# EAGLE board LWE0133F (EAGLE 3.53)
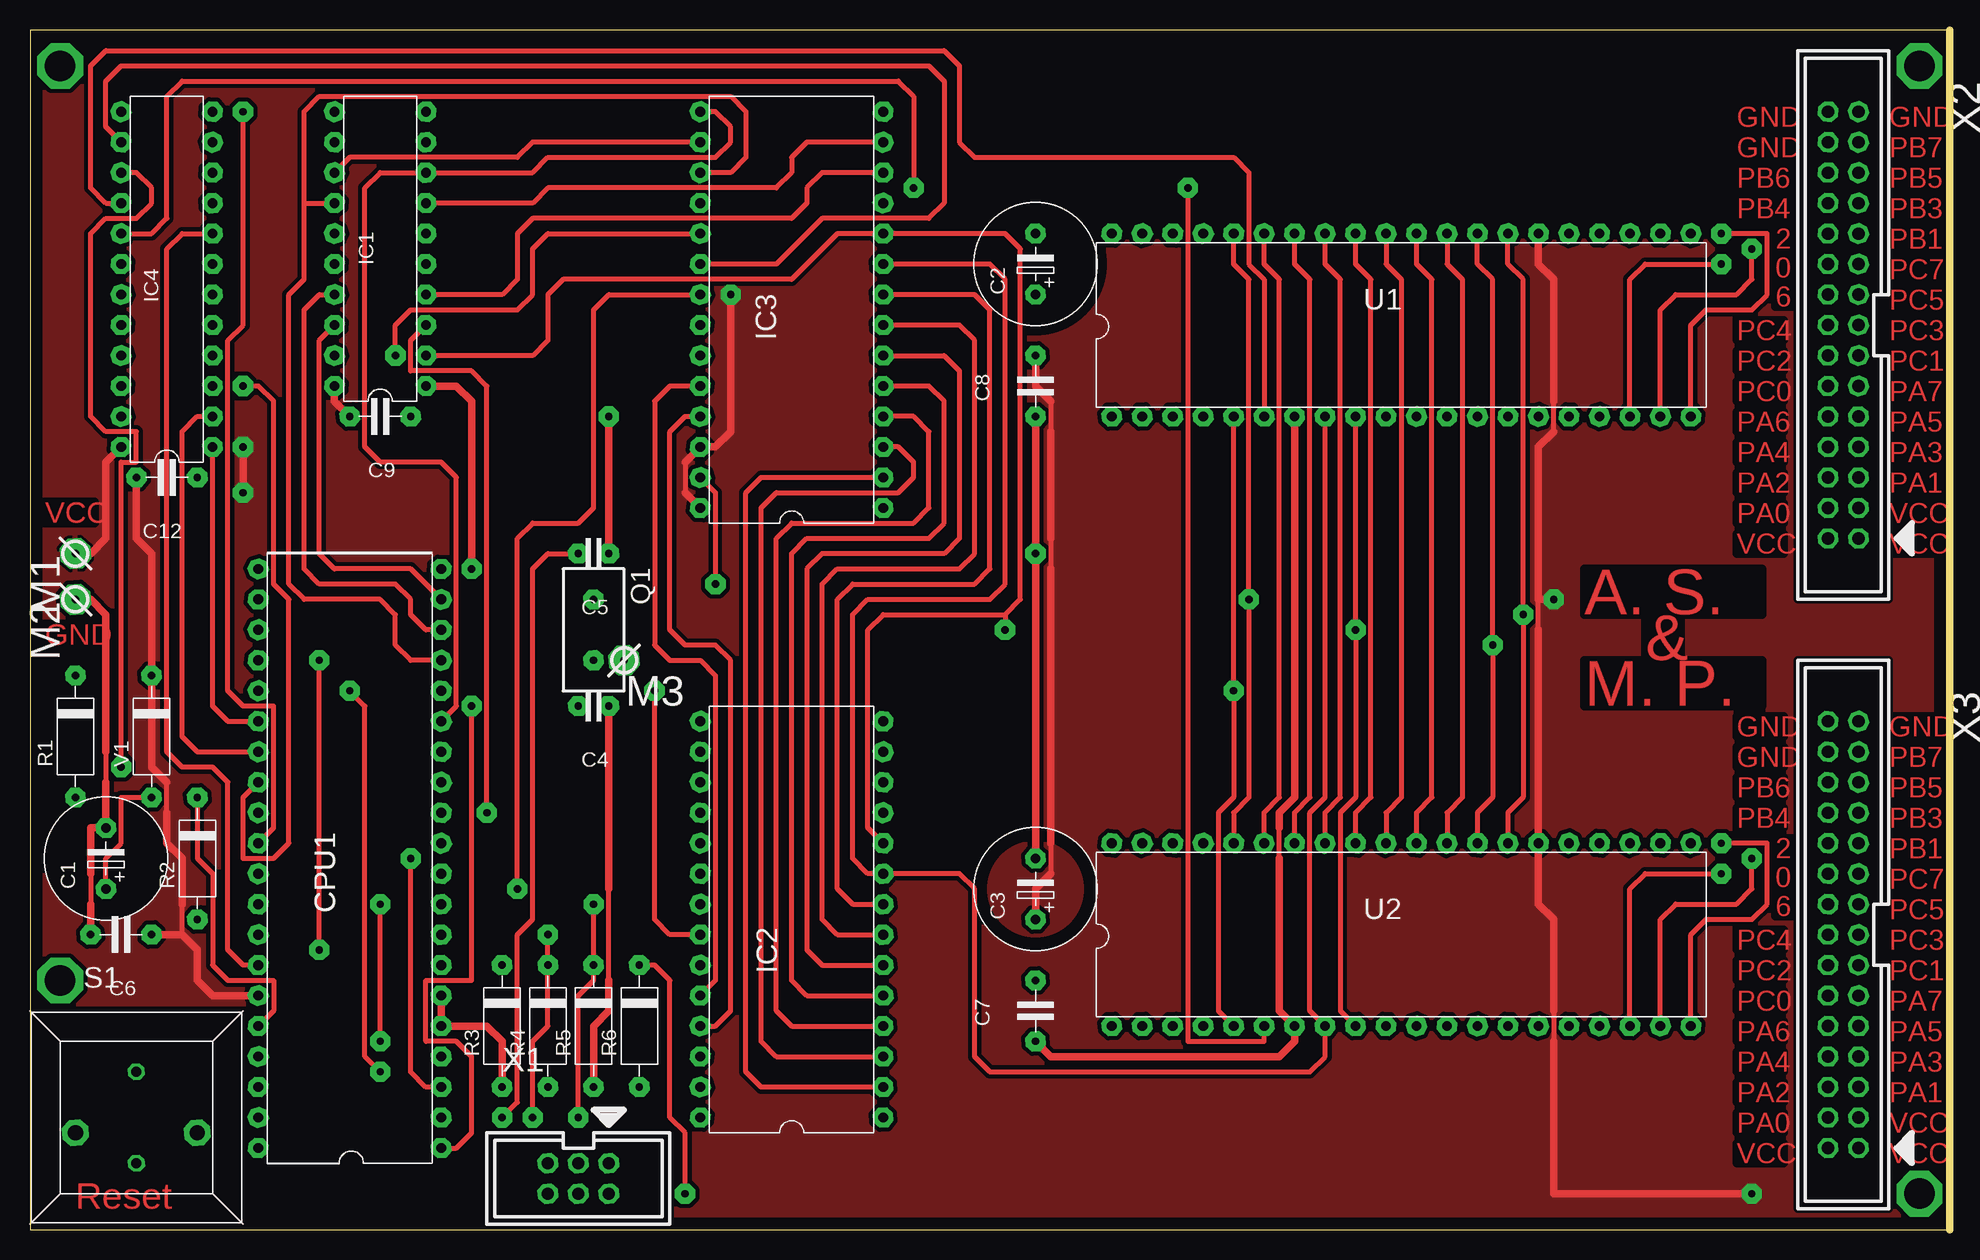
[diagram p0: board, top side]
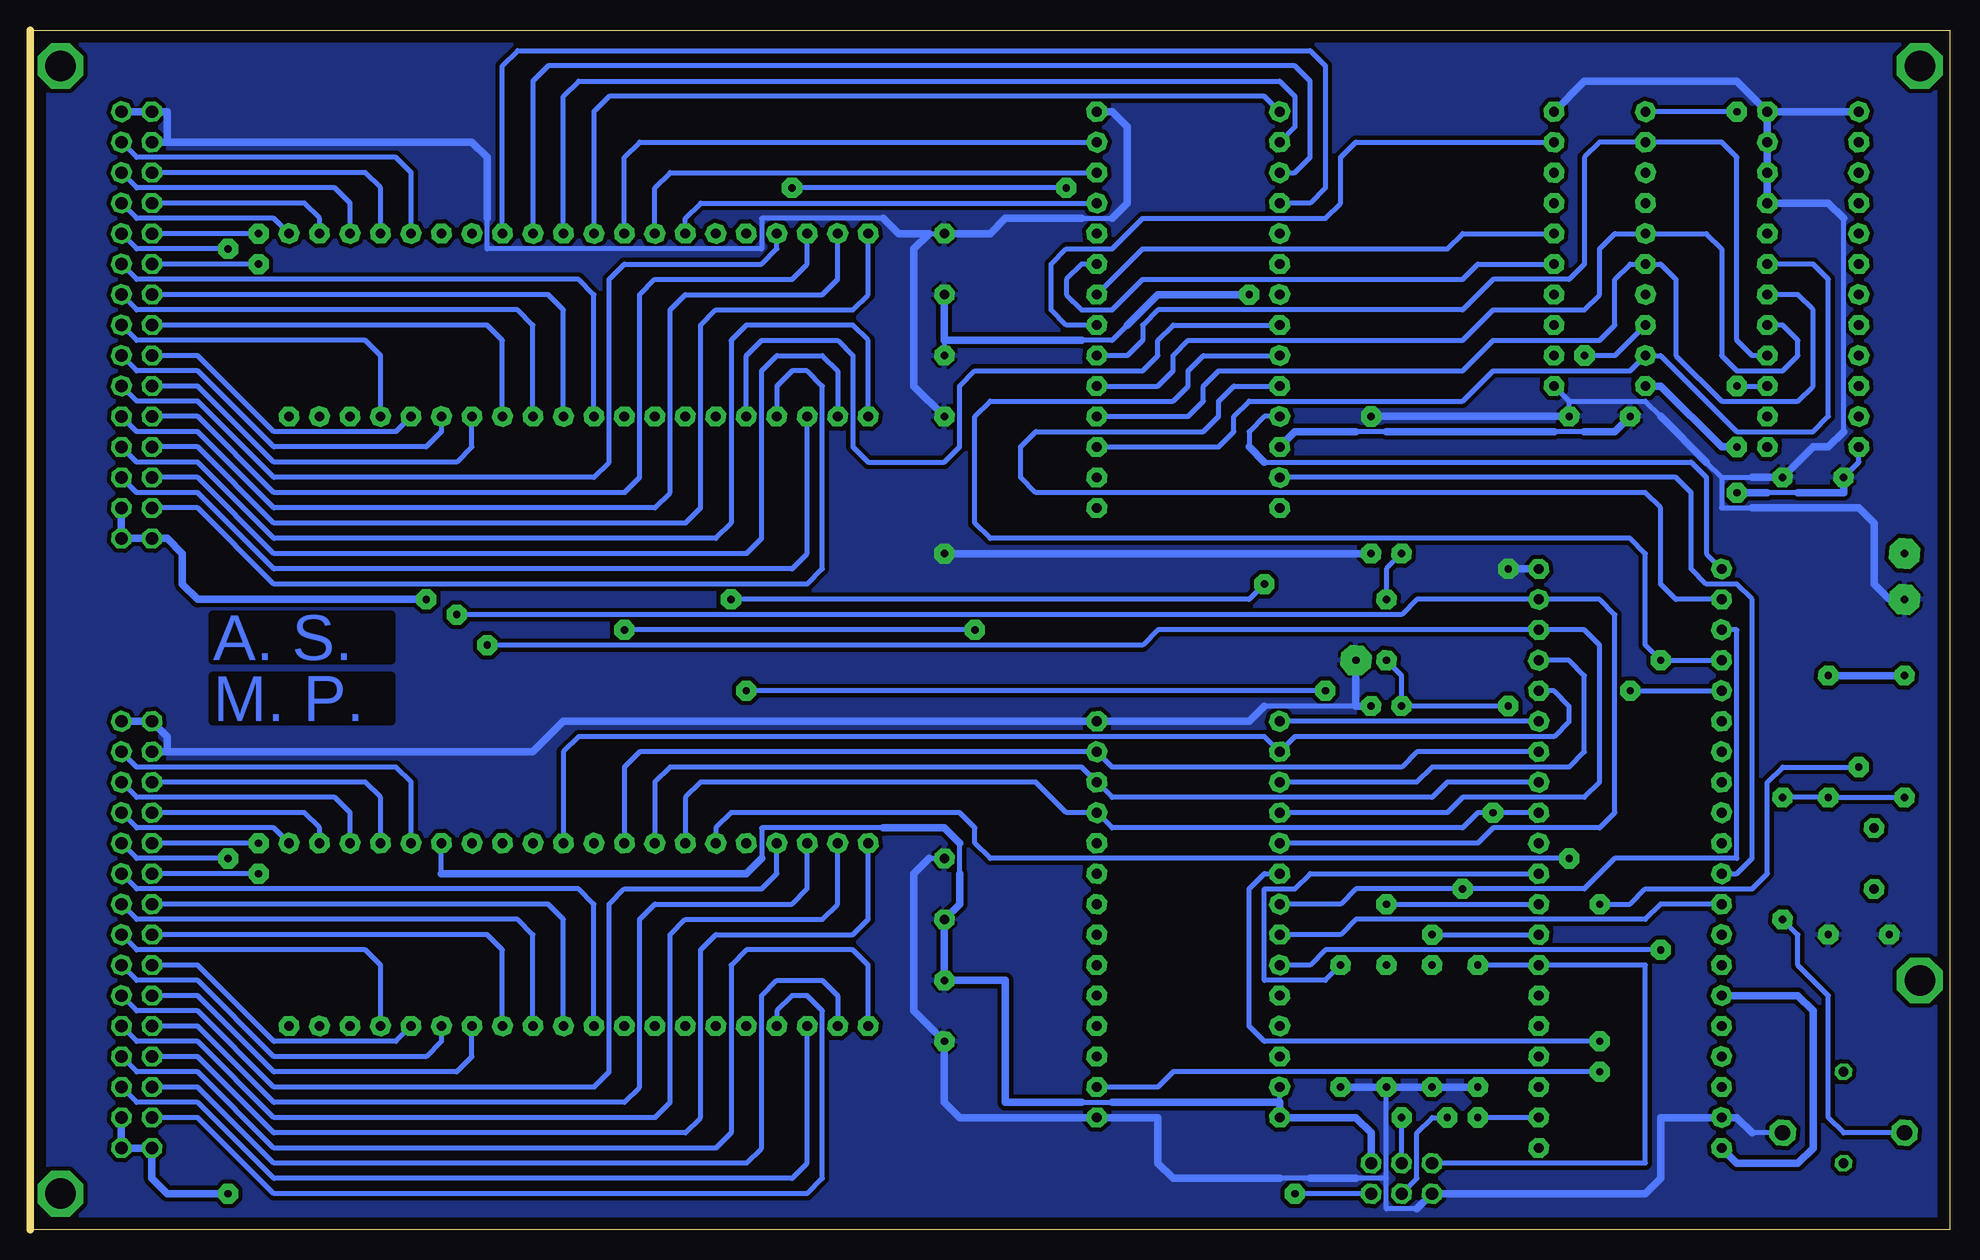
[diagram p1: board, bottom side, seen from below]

Size 159.99 x 99.97 mm. Coordinates in mm from the lower left corner, seen from the top.
Outline: 0,0 159.99,0 159.99,99.97 0,99.97 0,0
Copper layers used: Top, Bottom
tRestrict: area 38.1,0.5 to 53.3,8.1; area 147.3,52.5 to 154.9,98.2; area 147.3,1.7 to 154.9,47.4; area 38.1,0.5 to 53.3,8.1; area 43.2,44.9 to 50.8,55.1; area 0,0.5 to 17.8,18.2; area 1.7,26.4 to 10.9,35.5; area 78.4,75.1 to 89.2,85.9; area 79.2,23.8 to 88.4,33

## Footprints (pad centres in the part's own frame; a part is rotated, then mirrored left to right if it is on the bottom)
-5 = drill 0.813 pad 1.676 octagon:  -2.54,0;  2.54,0
2,5 = drill 0.61 pad 1.676 octagon:  -1.27,0;  1.27,0
5 = drill 0.61 pad 1.676 octagon:  -2.54,0;  2.54,0
L-40 = drill 0.813 pad 1.676 octagon:  -24.13,-7.62;  -21.59,-7.62;  -8.89,-7.62;  -6.35,-7.62;  -19.05,-7.62;  -16.51,-7.62;  -11.43,-7.62;  -13.97,-7.62;  -3.81,-7.62;  -1.27,-7.62;  1.27,-7.62;  3.81,-7.62;  6.35,-7.62;  8.89,-7.62;  11.43,-7.62;  13.97,-7.62;  16.51,-7.62;  19.05,-7.62;  21.59,-7.62;  24.13,-7.62;  24.13,7.62;  21.59,7.62;  19.05,7.62;  16.51,7.62;  13.97,7.62;  11.43,7.62;  8.89,7.62;  6.35,7.62;  3.81,7.62;  1.27,7.62;  -1.27,7.62;  -3.81,7.62;  -6.35,7.62;  -8.89,7.62;  -11.43,7.62;  -13.97,7.62;  -16.51,7.62;  -19.05,7.62;  -21.59,7.62;  -24.13,7.62
L-20 = drill 0.813 pad 1.676 octagon:  -11.43,-3.81;  -8.89,-3.81;  3.81,-3.81;  6.35,-3.81;  -6.35,-3.81;  -3.81,-3.81;  1.27,-3.81;  -1.27,-3.81;  8.89,-3.81;  11.43,-3.81;  11.43,3.81;  8.89,3.81;  6.35,3.81;  3.81,3.81;  1.27,3.81;  -1.27,3.81;  -3.81,3.81;  -6.35,3.81;  -8.89,3.81;  -11.43,3.81
L-28 = drill 0.813 pad 1.676 octagon:  -16.51,-7.62;  -13.97,-7.62;  -1.27,-7.62;  1.27,-7.62;  -11.43,-7.62;  -8.89,-7.62;  -3.81,-7.62;  -6.35,-7.62;  3.81,-7.62;  6.35,-7.62;  8.89,-7.62;  11.43,-7.62;  13.97,-7.62;  16.51,-7.62;  16.51,7.62;  13.97,7.62;  11.43,7.62;  8.89,7.62;  6.35,7.62;  3.81,7.62;  1.27,7.62;  -1.27,7.62;  -3.81,7.62;  -6.35,7.62;  -8.89,7.62;  -11.43,7.62;  -13.97,7.62;  -16.51,7.62
L-24S = drill 0.813 pad 1.676 octagon:  -13.97,-3.81;  -11.43,-3.81;  1.27,-3.81;  3.81,-3.81;  -8.89,-3.81;  -6.35,-3.81;  -1.27,-3.81;  -3.81,-3.81;  6.35,-3.81;  8.89,-3.81;  11.43,-3.81;  13.97,-3.81;  13.97,3.81;  11.43,3.81;  8.89,3.81;  6.35,3.81;  3.81,3.81;  1.27,3.81;  -1.27,3.81;  -3.81,3.81;  -6.35,3.81;  -8.89,3.81;  -11.43,3.81;  -13.97,3.81
TSTIFT = drill 0.61 pad 2.54 octagon:  0,0
ARZ = drill 0.61 pad 1.676 octagon:  -2.54,0;  2.54,0
10 = drill 0.61 pad 1.676 octagon:  -5.08,0;  5.08,0
GI-T = drill 0.813 pad 1.397 octagon:  1.27,-2.54;  1.27,-10.16 | drill 1.27 pad 2.184 octagon:  -3.81,-7.62;  6.35,-7.62
ABA6 = drill 1.016 pad 1.676 octagon:  -2.54,-1.27;  2.54,-1.27;  2.54,1.27;  -2.54,1.27;  0,1.27;  0,-1.27
ABA30 = drill 1.016 pad 1.676 octagon:  -17.78,-1.27;  -15.24,-1.27;  -12.7,-1.27;  -10.16,-1.27;  -7.62,-1.27;  -7.62,1.27;  -10.16,1.27;  -12.7,1.27;  -15.24,1.27;  -17.78,1.27;  -2.54,1.27;  -2.54,-1.27;  0,1.27;  0,-1.27;  2.54,-1.27;  7.62,-1.27;  10.16,-1.27;  10.16,1.27;  7.62,1.27;  2.54,1.27;  12.7,-1.27;  12.7,1.27;  15.24,-1.27;  17.78,-1.27;  17.78,1.27;  15.24,1.27;  -5.08,1.27;  -5.08,-1.27;  5.08,1.27;  5.08,-1.27

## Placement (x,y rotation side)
C1  4æ7  [-5]  6.32,30.94 90 top
C2  4æ7  [-5]  83.79,80.47 90 top
C3  4æ7  [-5]  83.79,28.4 90 top
C4  15pF  [2,5]  46.96,43.64 180 top
C5  15pF  [2,5]  46.96,56.34 180 top
C6  22nF  [5]  7.59,24.59 180 top
C7  22nF  [5]  83.79,18.24 90 top
C8  22nF  [5]  83.79,70.31 90 top
C9  22nF  [5]  29.18,67.77 180 top
C12  22nF  [5]  11.4,62.69 180 top
CPU1  8085  [L-40]  26.64,30.94 90 top
IC1  74373  [L-20]  29.18,81.74 90 top
IC2  2764  [L-28]  63.47,25.86 90 top
IC3  6264A  [L-28]  63.47,76.66 90 top
IC4  22V10  [L-24S]  11.4,79.2 90 top
M1  LTSTIFT  [TSTIFT]  3.78,56.34 90 top
M2  LTSTIFT  [TSTIFT]  3.78,52.53 90 top
M3  LTSTIFT  [TSTIFT]  49.5,47.45 180 top
Q1  6 MHz  [ARZ]  46.96,49.99 270 top
R1  47k  [10]  3.78,41.1 90 top
R2  1k  [10]  13.94,30.94 90 top
R3  10K  [10]  39.34,16.97 90 top
R4  10K  [10]  43.15,16.97 90 top
R5  10K  [10]  46.96,16.97 90 top
R6  10K  [10]  50.77,16.97 90 top
S1  DIGI-T  [GI-T]  7.59,15.7 0 top
U1  82C55A  [L-40]  114.27,75.39 0 top
U2  82C55A  [L-40]  114.27,24.59 0 top
V1  BAT4148  [10]  10.13,41.1 90 top
X1  FLABA6  [ABA6]  45.69,4.27 0 top
X2  FLABA30  [ABA30]  151.1,75.39 270 top
X3  FLABA30  [ABA30]  151.1,24.59 270 top

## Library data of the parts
C1-C9 C12 Q1 R1-R6 V1 = DISCRETE
CPU1 = INEMBED
IC1 = 74XXX
IC2 = MEMORY
IC3 = MEMHITCH
IC4 = PAL
M1-M3 X1-X3 = CONNECT
S1 = SPECIAL
U1 U2 = HARRIS

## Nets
AD0: CPU1. IC1. IC2. IC3. U1. U2.
AD1: CPU1. IC1. IC2. IC3. U1. U2.
AD2: CPU1. IC1. IC2. IC3. U1. U2.
AD3: CPU1. IC1. IC2. IC3. U1. U2.
AD4: CPU1. IC1. IC2. IC3. U1. U2.
AD5: CPU1. IC1. IC2. IC3. U1. U2.
AD6: CPU1. IC1. IC2. IC3. U1. U2.
AD7: CPU1. IC1. IC2. IC3. U1. U2.
ADR0: IC1. IC2. IC3. U1. U2.
ADR1: IC1. IC2. IC3. U1. U2.
ADR2: IC1. IC2. IC3.
ADR3: IC1. IC2. IC3.
ADR4: IC1. IC2. IC3. IC4.
ADR5: IC1. IC2. IC3. IC4.
ADR6: IC1. IC2. IC3. IC4.
ADR7: IC1. IC2. IC3. IC4.
ADR8: CPU1. IC2. IC3.
ADR9: CPU1. IC2. IC3.
ADR10: CPU1. IC2. IC3.
ADR11: CPU1. IC2. IC3.
ADR12: CPU1. IC2. IC3.
ADR13: CPU1. IC4.
ADR14: CPU1. IC4.
ADR15: CPU1. IC4.
ADRLATCH: CPU1. IC1.
CS-EPROM: IC2. IC4.
CS-PIO1: IC4. U1.
CS-PIO2: IC4. U2.
CS-RAM: IC3. IC4.
GND: C1. C2. C3. C4. C5. C6. C7. C8. C9. C12. CPU1. IC1. IC2. IC3. IC4. M2. M3. R3. R4. R5. R6. S1. U1. U2. X1. X2. X3.
INT0: CPU1. R6. X1.
INT1: CPU1. R5. X1.
INT2: CPU1. R4. X1.
INT3: CPU1. R3. X1.
IO/M: CPU1. IC4.
N$54: C5. CPU1. Q1.
N$55: C4. CPU1. Q1.
N$57: R2. S1.
PA0-1: U1. X2.
PA0-2: U2. X3.
PA1-1: U1. X2.
PA1-2: U2. X3.
PA2-1: U1. X2.
PA2-2: U2. X3.
PA3-1: U1. X2.
PA3-2: U2. X3.
PA4-1: U1. X2.
PA4-2: U2. X3.
PA5-1: U1. X2.
PA5-2: U2. X3.
PA6-1: U1. X2.
PA6-2: U2. X3.
PA7-1: U1. X2.
PA7-2: U2. X3.
PB0-1: U1. X2.
PB0-2: U2. X3.
PB1-1: U1. X2.
PB1-2: U2. X3.
PB2-1: U1. X2.
PB2-2: U2. X3.
PB3-1: U1. X2.
PB3-2: U2. X3.
PB4-1: U1. X2.
PB4-2: U2. X3.
PB5-1: U1. X2.
PB5-2: U2. X3.
PB6-1: U1. X2.
PB6-2: U2. X3.
PB7-1: U1. X2.
PB7-2: U2. X3.
PC0-1: U1. X2.
PC0-2: U2. X3.
PC1-1: U1. X2.
PC1-2: U2. X3.
PC2-1: U1. X2.
PC2-2: U2. X3.
PC3-1: U1. X2.
PC3-2: U2. X3.
PC4-1: U1. X2.
PC4-2: U2. X3.
PC5-1: U1. X2.
PC5-2: U2. X3.
PC6-1: U1. X2.
PC6-2: U2. X3.
PC7-1: U1. X2.
PC7-2: U2. X3.
READ: CPU1. IC2. IC3. U1. U2.
RESET: CPU1. U1. U2.
RESET-IN: C1. CPU1. R1. R2. V1.
VCC: C2. C3. C6. C7. C8. C9. C12. CPU1. IC1. IC2. IC3. IC4. M1. R1. U1. U2. V1. X1. X2. X3.
WRITE: CPU1. IC3. U1. U2.

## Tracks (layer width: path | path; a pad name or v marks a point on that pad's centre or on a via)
AD0  (via drill 0.61 pad 1.68)
  Top 0.406: 105.38,83.01 105.38,80.47 106.65,79.2 106.65,36.02 105.38,34.75 105.38,32.21 | 32.99,75.39 31.72,74.12 31.72,71.58 36.8,71.58 38.07,70.31 v38.07,34.75
  Bottom 0.406: 105.38,83.01 105.38,84.28 104.11,85.55 71.09,85.55 | 105.38,32.21 105.38,36.02 104.11,37.29 76.17,37.29 73.63,34.75 71.09,34.75 69.82,33.48 40.61,33.48 39.34,34.75 v38.07,34.75 34.26,34.75
AD1
  Top 0.406: 107.92,32.21 107.92,34.75 109.19,36.02 109.19,79.2 107.92,80.47 107.92,83.01 | 32.99,77.93 39.34,77.93 40.61,79.2 40.61,83.01 41.88,84.28 63.47,84.28 64.74,85.55 64.74,86.82 66.01,88.09 71.09,88.09
  Bottom 0.406: 107.92,83.01 107.92,86.82 106.65,88.09 71.09,88.09 | 34.26,37.29 41.88,37.29 43.15,36.02 69.82,36.02 71.09,37.29 72.36,38.56 106.65,38.56 107.92,37.29 107.92,32.21
AD2
  Top 0.406: 110.46,32.21 110.46,34.75 111.73,36.02 111.73,79.2 110.46,80.47 110.46,83.01 | 32.99,85.55 41.88,85.55 43.15,86.82 62.2,86.82 63.47,88.09 63.47,89.36 64.74,90.63 71.09,90.63
  Bottom 0.406: 110.46,83.01 110.46,89.36 109.19,90.63 71.09,90.63 | 34.26,39.83 44.42,39.83 45.69,38.56 69.82,38.56 71.09,39.83 109.19,39.83 110.46,38.56 110.46,32.21
AD3
  Top 0.406: 113,83.01 113,80.47 114.27,79.2 114.27,36.02 113,34.75 113,32.21 | 55.85,93.17 57.12,93.17 58.39,91.9 58.39,90.63 57.12,89.36 43.15,89.36 41.88,88.09 32.99,88.09 29.18,88.09 27.91,86.82 27.91,65.23 29.18,63.96 34.26,63.96 35.53,62.69 35.53,43.64 34.26,42.37
  Bottom 0.406: 113,83.01 113,93.17 111.73,94.44 57.12,94.44 55.85,93.17 | 34.26,42.37 55.85,42.37
AD4
  Top 0.406: 115.54,83.01 115.54,80.47 116.81,79.2 116.81,36.02 115.54,34.75 115.54,32.21 | 55.85,90.63 41.88,90.63 40.61,89.36 26.64,89.36 25.37,88.09
  Bottom 0.406: 115.54,83.01 115.54,94.44 114.27,95.71 55.85,95.71 54.58,94.44 54.58,91.9 55.85,90.63 | 115.54,32.21 115.54,39.83 114.27,41.1 57.12,41.1 55.85,39.83 54.58,41.1 32.99,41.1 31.72,42.37 31.72,43.64 32.99,44.91 34.26,44.91
AD5
  Top 0.406: 118.08,83.01 118.08,80.47 119.35,79.2 119.35,36.02 118.08,34.75 118.08,32.21 | 22.83,85.55 22.83,93.17 24.1,94.44 58.39,94.44 59.66,93.17 59.66,89.36 58.39,88.09 55.85,88.09 | 22.83,85.55 25.37,85.55 | 22.83,85.55 22.83,79.2 21.56,77.93 21.56,53.8 22.83,52.53 29.18,52.53 30.45,51.26 30.45,48.72 31.72,47.45 34.26,47.45
  Bottom 0.406: 118.08,83.01 118.08,95.71 116.81,96.98 54.58,96.98 53.31,95.71 53.31,89.36 54.58,88.09 55.85,88.09 | 34.26,47.45 31.72,47.45 30.45,46.18 30.45,39.83 31.72,38.56 43.15,38.56 44.42,37.29 55.85,37.29
AD6  (via drill 0.61 pad 1.68)
  Top 0.406: 120.62,83.01 120.62,80.47 121.89,79.2 v121.89,48.72 121.89,36.02 120.62,34.75 120.62,32.21 | 25.37,77.93 24.1,77.93 22.83,76.66 22.83,55.07 24.1,53.8 30.45,53.8 31.72,52.53 31.72,51.26 32.99,49.99 34.26,49.99
  Bottom 0.406: 120.62,83.01 120.62,96.98 119.35,98.25 53.31,98.25 52.04,96.98 52.04,86.82 53.31,85.55 55.85,85.55 | 55.85,34.75 41.88,34.75 40.61,36.02 30.45,36.02 29.18,37.29 29.18,48.72 30.45,49.99 34.26,49.99 66.01,49.99 67.28,48.72 v121.89,48.72
AD7  (via drill 0.61 pad 1.68)
  Top 0.406: 123.16,83.01 123.16,80.47 124.43,79.2 v124.43,51.26 124.43,36.02 123.16,34.75 123.16,32.21 | 25.37,75.39 24.1,74.12 24.1,56.34 25.37,55.07 31.72,55.07 34.26,52.53 | 55.85,83.01 43.15,83.01 41.88,81.74 41.88,77.93 40.61,76.66 31.72,76.66 30.45,75.39 v30.45,72.85
  Bottom 0.406: 55.85,32.21 39.34,32.21 38.07,33.48 29.18,33.48 27.91,34.75 27.91,51.26 29.18,52.53 34.26,52.53 44.42,52.53 45.69,51.26 v124.43,51.26 | v30.45,72.85 27.91,72.85 25.37,75.39
ADR0  (via drill 0.61 pad 1.68)
  Top 0.406: 110.46,67.77 v110.46,49.99 110.46,36.02 109.19,34.75 109.19,18.24 110.46,16.97 | 71.09,32.21 69.82,33.48 69.82,49.99 71.09,51.26 81.25,51.26 | 81.25,51.26 82.52,52.53 82.52,81.74 81.25,83.01 71.09,83.01 67.28,83.01 63.47,79.2 44.42,79.2 43.15,77.93 43.15,74.12 41.88,72.85 32.99,72.85 | 81.25,51.26 v81.25,49.99
  Bottom 0.406: v81.25,49.99 v110.46,49.99
ADR1
  Top 0.406: 107.92,67.77 107.92,36.02 106.65,34.75 106.65,18.24 107.92,16.97 107.92,14.43 106.65,13.16 79.98,13.16 78.71,14.43 78.71,28.4 77.44,29.67 71.09,29.67 69.82,29.67 68.55,30.94 68.55,51.26 69.82,52.53 79.98,52.53 81.25,53.8 81.25,79.2 79.98,80.47 71.09,80.47
  Bottom 0.406: 71.09,80.47 72.36,80.47 73.63,79.2 73.63,77.93 72.36,76.66 69.82,76.66 67.28,79.2 40.61,79.2 39.34,80.47 32.99,80.47
ADR2
  Top 0.406: 71.09,27.13 68.55,27.13 67.28,28.4 67.28,52.53 68.55,53.8 78.71,53.8 79.98,55.07 79.98,76.66 78.71,77.93 71.09,77.93
  Bottom 0.406: 71.09,77.93 67.28,81.74 41.88,81.74 40.61,83.01 32.99,83.01
ADR3
  Top 0.406: 71.09,24.59 67.28,24.59 66.01,25.86 66.01,53.8 67.28,55.07 77.44,55.07 78.71,56.34 78.71,74.12 77.44,75.39 71.09,75.39
  Bottom 0.406: 71.09,75.39 73.63,75.39 74.9,76.66 74.9,80.47 73.63,81.74 69.82,81.74 67.28,84.28 52.04,84.28 50.77,85.55 50.77,89.36 49.5,90.63 32.99,90.63
ADR4
  Top 0.406: 71.09,22.05 66.01,22.05 64.74,23.32 64.74,55.07 66.01,56.34 76.17,56.34 77.44,57.61 77.44,71.58 76.17,72.85 71.09,72.85
  Bottom 0.406: 71.09,72.85 68.55,72.85 67.28,74.12 67.28,75.39 66.01,76.66 40.61,76.66 38.07,79.2 31.72,79.2 30.45,80.47 30.45,89.36 29.18,90.63 25.37,90.63 19.02,90.63 17.75,89.36 17.75,74.12 16.48,72.85 15.21,72.85
ADR5
  Top 0.406: 71.09,19.51 64.74,19.51 63.47,20.78 63.47,56.34 64.74,57.61 74.9,57.61 76.17,58.88 76.17,69.04 74.9,70.31 71.09,70.31
  Bottom 0.406: 71.09,70.31 66.01,70.31 64.74,71.58 64.74,72.85 63.47,74.12 40.61,74.12 38.07,76.66 30.45,76.66 29.18,77.93 29.18,81.74 27.91,83.01 25.37,83.01 20.29,83.01 19.02,81.74 19.02,72.85 17.75,71.58 13.94,71.58 12.67,72.85 12.67,74.12 13.94,75.39 15.21,75.39
ADR6
  Top 0.406: 71.09,16.97 63.47,16.97 62.2,18.24 62.2,57.61 63.47,58.88 73.63,58.88 74.9,60.15 74.9,66.5 73.63,67.77 71.09,67.77
  Bottom 0.406: 71.09,67.77 63.47,67.77 62.2,69.04 62.2,70.31 60.93,71.58 40.61,71.58 38.07,74.12 29.18,74.12 27.91,75.39 27.91,79.2 26.64,80.47 25.37,80.47 24.1,80.47 22.83,79.2 22.83,72.85 19.02,69.04 12.67,69.04 11.4,70.31 11.4,76.66 12.67,77.93 15.21,77.93
ADR7
  Top 0.406: 71.09,65.23 72.36,65.23 73.63,63.96 73.63,62.69 72.36,61.42 62.2,61.42 60.93,60.15 60.93,15.7 62.2,14.43 71.09,14.43
  Bottom 0.406: 71.09,65.23 60.93,65.23 59.66,66.5 59.66,67.77 58.39,69.04 40.61,69.04 38.07,71.58 26.64,71.58 25.37,72.85 24.1,72.85 17.75,66.5 11.4,66.5 10.13,67.77 10.13,79.2 11.4,80.47 15.21,80.47
ADR8
  Top 0.406: 55.85,16.97 57.12,16.97 58.39,18.24 58.39,47.45 57.12,48.72 54.58,48.72 53.31,49.99 53.31,66.5 54.58,67.77 55.85,67.77
  Bottom 0.406: 19.02,55.07 20.29,56.34 20.29,62.69 21.56,63.96 57.12,63.96 | 58.39,65.23 58.39,66.5 57.12,67.77 55.85,67.77
  Bottom 0.61: 58.39,65.23 57.12,63.96
ADR9
  Top 0.406: 55.85,19.51 57.12,20.78 57.12,46.18 55.85,47.45 53.31,47.45 52.04,48.72 52.04,69.04 53.31,70.31 55.85,70.31
  Bottom 0.406: 55.85,70.31 59.66,70.31 60.93,69.04 60.93,67.77 62.2,66.5 76.17,66.5 77.44,65.23 77.44,62.69 76.17,61.42 25.37,61.42 24.1,60.15 24.1,53.8 22.83,52.53 19.02,52.53
ADR10  (via drill 0.61 pad 1.68)
  Top 0.406: 55.85,77.93 48.23,77.93 46.96,76.66 46.96,60.15 45.69,58.88 41.88,58.88 40.61,57.61 v40.61,28.4
  Bottom 0.406: 19.02,49.99 17.75,49.99 17.75,30.94 27.91,30.94 30.45,28.4 v40.61,28.4 49.5,28.4 50.77,27.13 55.85,27.13
ADR11  (via drill 0.61 pad 1.68)
  Top 0.406: v24.1,23.32 v24.1,47.45
  Bottom 0.406: 55.85,72.85 62.2,72.85 63.47,71.58 63.47,70.31 64.74,69.04 79.98,69.04 81.25,67.77 81.25,58.88 79.98,57.61 26.64,57.61 25.37,56.34 25.37,48.72 v24.1,47.45 19.02,47.45 | 55.85,22.05 53.31,22.05 52.04,23.32 v24.1,23.32
ADR12  (via drill 0.61 pad 1.68)
  Top 0.406: 71.09,11.89 60.93,11.89 59.66,13.16 59.66,61.42 60.93,62.69 71.09,62.69 | v26.64,44.91 27.91,43.64 27.91,14.43 v29.18,13.16
  Bottom 0.406: v26.64,44.91 19.02,44.91 | v29.18,13.16 64.74,13.16 66.01,11.89 71.09,11.89
ADR13
  Top 0.406: 19.02,42.37 16.48,42.37 15.21,43.64 15.21,65.23
ADR14
  Top 0.406: 19.02,39.83 13.94,39.83 12.67,41.1 12.67,66.5 13.94,67.77 15.21,67.77
ADR15  (via drill 0.61 pad 1.68)
  Top 0.406: 19.02,37.29 17.75,36.02 17.75,30.94 20.29,30.94 21.56,32.21 21.56,52.53 20.29,53.8 20.29,69.04 19.02,70.31 v17.75,70.31
  Bottom 0.406: v17.75,70.31 15.21,70.31
ADRLATCH  (via drill 0.61 pad 1.68)
  Top 0.406: 19.02,32.21 20.29,33.48 20.29,43.64 17.75,43.64 16.48,44.91 16.48,74.12 17.75,75.39 v17.75,93.17
  Bottom 0.406: v17.75,93.17 25.37,93.17
CS-EPROM  (via drill 0.61 pad 1.68)
  Top 0.406: v29.18,15.7 v29.18,27.13 | v7.59,38.56 7.59,63.96 8.86,63.96 8.86,66.5 6.32,66.5 5.05,67.77 5.05,83.01 6.32,84.28 8.86,84.28 10.13,85.55 10.13,86.82 8.86,88.09 7.59,88.09
  Bottom 0.406: 55.85,29.67 57.12,29.67 58.39,28.4 58.39,16.97 57.12,15.7 v29.18,15.7 | v29.18,27.13 26.64,27.13 25.37,28.4 16.48,28.4 15.21,29.67 15.21,37.29 13.94,38.56 v7.59,38.56
CS-PIO1
  Top 0.406: 7.59,85.55 6.32,85.55 5.05,86.82 5.05,96.98 6.32,98.25 76.17,98.25 77.44,96.98 77.44,90.63 78.71,89.36 100.3,89.36 101.57,88.09 101.57,80.47 102.84,79.2 102.84,67.77
CS-PIO2  (via drill 0.61 pad 1.68)
  Top 0.406: 7.59,83.01 10.13,83.01 11.4,84.28 11.4,94.44 12.67,95.71 72.36,95.71 73.63,94.44 v73.63,86.82 | v96.49,86.82 96.49,15.7 102.84,15.7 102.84,16.97
  Bottom 0.406: v73.63,86.82 v96.49,86.82
CS-RAM
  Top 0.406: 55.85,80.47 62.2,80.47 66.01,84.28 74.9,84.28 76.17,85.55 76.17,95.71 74.9,96.98 7.59,96.98 6.32,95.71 6.32,91.9 7.59,90.63
GND  (via drill 0.61 pad 1.68)
  Top 0.406: 5.05,29.67 5.05,27.13 | 6.32,39.83 6.32,37.29 | 104.11,30.94 104.11,33.48 | 48.23,20.78 48.23,28.4
  Top 0.61: 83.79,15.7 85.06,14.43 104.11,14.43 105.38,15.7 105.38,16.97 104.11,18.24 104.11,30.94 | 34.26,19.51 34.26,16.97 38.07,16.97 39.34,15.7 39.34,11.89 | 5.05,27.13 C6. | 6.32,39.83 6.32,51.26 5.05,52.53 M2. | 6.32,37.29 C1. 5.05,33.48 5.05,29.67 | 32.99,70.31 35.53,70.31 36.8,69.04 v36.8,55.07 | 48.23,56.34 v48.23,67.77 | 105.38,67.77 105.38,36.02 104.11,34.75 104.11,33.48 | 83.79,67.77 v83.79,56.34 C3. | 48.23,20.78 48.23,18.24 46.96,16.97 46.96,11.89 | 48.23,28.4 48.23,43.64
  Bottom 0.406: 72.36,84.28 69.82,84.28 | 85.06,83.01 C2. | 85.06,30.94 C3. | 31.72,67.77 31.72,69.04 | 31.72,69.04 32.99,70.31 | 19.02,62.69 16.48,62.69 | 20.29,63.96 19.02,62.69 | 24.1,67.77 25.37,69.04 31.72,69.04 | 8.86,66.5 8.86,84.28 | S1. 16.48,8.08 | 49.5,43.64 57.12,43.64 | 44.42,1.73 46.96,1.73 46.96,4.27 | 46.96,4.27 46.96,11.89 | 16.48,60.15 19.02,60.15 19.02,62.69 | 121.89,84.28 121.89,81.74 99.03,81.74 99.03,84.28 88.87,84.28 | 46.96,4.27 49.5,4.27 | 53.31,4.27 55.85,4.27
  Bottom 0.61: C2. 79.98,83.01 78.71,84.28 72.36,84.28 | 69.82,84.28 68.55,85.55 68.55,91.9 69.82,93.17 71.09,93.17 | 83.79,67.77 86.33,70.31 86.33,81.74 85.06,83.01 87.6,83.01 88.87,84.28 | 85.06,30.94 86.33,29.67 86.33,18.24 83.79,15.7 83.79,10.62 82.52,9.35 71.09,9.35 66.01,9.35 66.01,5.54 64.74,4.27 55.85,4.27 | 16.48,62.69 13.94,62.69 11.4,65.23 10.13,65.23 8.86,66.5 | 24.1,67.77 20.29,63.96 | 15.21,93.17 15.21,90.63 15.21,88.09 15.21,85.55 10.13,85.55 8.86,84.28 | 15.21,93.17 7.59,93.17 | 15.21,93.17 17.75,95.71 30.45,95.71 32.99,93.17 | 16.48,8.08 17.75,9.35 19.02,9.35 24.1,9.35 24.1,4.27 25.37,3 43.15,3 44.42,1.73 | 50.77,11.89 46.96,11.89 43.15,11.89 39.34,11.89 | 148.56,39.83 149.83,39.83 | 152.37,42.37 149.83,42.37 148.56,41.1 148.56,39.83 | 57.12,43.64 58.39,42.37 71.09,42.37 115.54,42.37 118.08,39.83 148.56,39.83 | 48.23,43.64 49.5,43.64 M3. | v36.8,55.07 34.26,55.07 | v48.23,67.77 31.72,67.77 | 16.48,60.15 7.59,60.15 6.32,58.88 6.32,53.8 5.05,52.53 M2. | 148.56,90.63 149.83,90.63 | 148.56,90.63 148.56,93.17 149.83,93.17 152.37,93.17 | 148.56,90.63 123.16,90.63 121.89,89.36 121.89,84.28 | v83.79,56.34 48.23,56.34 | 49.5,4.27 53.31,4.27
  pour Bottom (isolate 0.356): -0.03,99.52 159.99,99.52 159.99,0.46 -0.03,0.46
INT0  (via drill 0.61 pad 1.68)
  Top 0.406: v54.58,3 54.58,8.08 53.31,9.35 53.31,20.78 52.04,22.05 R6.
  Bottom 0.406: 48.23,3 v54.58,3 | 34.26,29.67 53.31,29.67 54.58,28.4 57.12,28.4 57.12,20.78 52.04,20.78 R6.
INT1  (via drill 0.61 pad 1.68)
  Top 0.406: v45.69,9.35 45.69,19.51 46.96,20.78 R5. v46.96,27.13
  Bottom 0.406: 45.69,5.54 v45.69,9.35 | v46.96,27.13 34.26,27.13
INT2  (via drill 0.61 pad 1.68)
  Top 0.406: v41.88,9.35 41.88,15.7 43.15,16.97 R4. v43.15,24.59
  Bottom 0.406: X1. 44.42,4.27 44.42,8.08 43.15,9.35 v41.88,9.35 | v43.15,24.59 34.26,24.59
INT3
  Bottom 0.406: R3. 34.26,22.05 25.37,22.05 25.37,5.54 43.15,5.54
IO/M
  Top 0.406: 19.02,22.05 17.75,22.05 16.48,23.32 16.48,37.29 15.21,38.56 12.67,38.56 11.4,39.83 11.4,81.74 12.67,83.01 15.21,83.01
N$1  (via drill 2.54 pad 3.81)
  other vias: 157.45,3
N$2  (via drill 2.54 pad 3.81)
  other vias: 157.45,96.98
N$3  (via drill 2.54 pad 3.81)
  other vias: 2.51,20.78
N$4  (via drill 2.54 pad 3.81)
  other vias: 2.51,96.98
N$54  (via drill 0.61 pad 1.68)
  Top 0.406: v39.34,9.35 40.61,10.62 40.61,24.59 41.88,25.86 41.88,55.07 43.15,56.34 C5.
  Bottom 0.406: 34.26,9.35 v39.34,9.35 | C5. 46.96,55.07 46.96,52.53
N$55  (via drill 0.61 pad 1.68)
  Top 0.406: 34.26,6.81 35.53,6.81 36.8,8.08 36.8,14.43 35.53,15.7 32.99,15.7 32.99,20.78 36.8,20.78 v36.8,43.64
  Bottom 0.406: v36.8,43.64 C4. 45.69,46.18 Q1.
N$57
  Bottom 0.406: 13.94,25.86 12.67,24.59 12.67,22.05 10.13,19.51 10.13,9.35 8.86,8.08 3.78,8.08
PA0-1
  Bottom 0.406: 97.76,67.77 97.76,70.31 96.49,71.58 95.22,71.58 93.95,70.31 93.95,55.07 95.22,53.8 139.67,53.8 146.02,60.15 149.83,60.15
PA0-2
  Bottom 0.406: 97.76,16.97 97.76,18.24 96.49,19.51 95.22,19.51 93.95,18.24 93.95,4.27 95.22,3 139.67,3 146.02,9.35 149.83,9.35
PA1-1
  Bottom 0.406: 95.22,67.77 95.22,56.34 96.49,55.07 139.67,55.07 146.02,61.42 151.1,61.42 152.37,62.69
PA1-2
  Bottom 0.406: 95.22,16.97 95.22,5.54 96.49,4.27 139.67,4.27 146.02,10.62 151.1,10.62 152.37,11.89
PA2-1
  Bottom 0.406: 92.68,67.77 92.68,71.58 93.95,72.85 97.76,72.85 99.03,71.58 99.03,57.61 100.3,56.34 139.67,56.34 146.02,62.69 149.83,62.69
PA2-2
  Bottom 0.406: 92.68,16.97 92.68,19.51 93.95,20.78 97.76,20.78 99.03,19.51 99.03,6.81 100.3,5.54 139.67,5.54 146.02,11.89 149.83,11.89
PA3-1
  Bottom 0.406: 90.14,67.77 90.14,74.12 91.41,75.39 100.3,75.39 101.57,74.12 101.57,58.88 102.84,57.61 139.67,57.61 146.02,63.96 151.1,63.96 152.37,65.23
PA3-2
  Bottom 0.406: 90.14,16.97 90.14,22.05 91.41,23.32 100.3,23.32 101.57,22.05 101.57,8.08 102.84,6.81 139.67,6.81 146.02,13.16 151.1,13.16 152.37,14.43
PA4-1
  Bottom 0.406: U1. 90.14,77.93 91.41,76.66 102.84,76.66 104.11,75.39 104.11,60.15 105.38,58.88 139.67,58.88 146.02,65.23 149.83,65.23
PA4-2
  Bottom 0.406: U2. 90.14,25.86 91.41,24.59 102.84,24.59 104.11,23.32 104.11,9.35 105.38,8.08 139.67,8.08 146.02,14.43 149.83,14.43
PA5-1
  Bottom 0.406: 92.68,83.01 92.68,79.2 93.95,77.93 105.38,77.93 106.65,76.66 106.65,61.42 107.92,60.15 139.67,60.15 146.02,66.5 151.1,66.5 152.37,67.77
PA5-2
  Bottom 0.406: 92.68,32.21 92.68,27.13 93.95,25.86 105.38,25.86 106.65,24.59 106.65,10.62 107.92,9.35 139.67,9.35 146.02,15.7 151.1,15.7 152.37,16.97
PA6-1
  Bottom 0.406: 95.22,83.01 95.22,80.47 96.49,79.2 107.92,79.2 109.19,77.93 109.19,62.69 110.46,61.42 139.67,61.42 146.02,67.77 149.83,67.77
PA6-2
  Bottom 0.406: 95.22,32.21 95.22,28.4 96.49,27.13 107.92,27.13 109.19,25.86 109.19,11.89 110.46,10.62 139.67,10.62 146.02,16.97 149.83,16.97
PA7-1
  Bottom 0.406: 97.76,83.01 97.76,81.74 99.03,80.47 110.46,80.47 111.73,79.2 111.73,63.96 113,62.69 139.67,62.69 146.02,69.04 151.1,69.04 152.37,70.31
PA7-2
  Bottom 0.406: 97.76,32.21 97.76,29.67 99.03,28.4 110.46,28.4 111.73,27.13 111.73,13.16 113,11.89 139.67,11.89 146.02,18.24 151.1,18.24 152.37,19.51
PB0-1  (via drill 0.61 pad 1.68)
  Top 0.406: 133.32,67.77 133.32,79.2 134.59,80.47 v140.94,80.47
  Bottom 0.406: v140.94,80.47 149.83,80.47
PB0-2  (via drill 0.61 pad 1.68)
  Top 0.406: 133.32,16.97 133.32,28.4 134.59,29.67 v140.94,29.67
  Bottom 0.406: v140.94,29.67 149.83,29.67
PB1-1  (via drill 0.61 pad 1.68)
  Top 0.406: 135.86,67.77 135.86,76.66 137.13,77.93 142.21,77.93 143.48,79.2 v143.48,81.74
  Bottom 0.406: v143.48,81.74 151.1,81.74 152.37,83.01
PB1-2  (via drill 0.61 pad 1.68)
  Top 0.406: 135.86,16.97 135.86,25.86 137.13,27.13 142.21,27.13 143.48,28.4 v143.48,30.94
  Bottom 0.406: v143.48,30.94 151.1,30.94 152.37,32.21
PB2-1  (via drill 0.61 pad 1.68)
  Top 0.406: 138.4,67.77 138.4,75.39 139.67,76.66 143.48,76.66 144.75,77.93 144.75,83.01 v140.94,83.01
  Bottom 0.406: v140.94,83.01 149.83,83.01
PB2-2  (via drill 0.61 pad 1.68)
  Top 0.406: 138.4,16.97 138.4,24.59 139.67,25.86 143.48,25.86 144.75,27.13 144.75,32.21 v140.94,32.21
  Bottom 0.406: v140.94,32.21 149.83,32.21
PB3-1
  Bottom 0.406: 138.4,83.01 139.67,84.28 151.1,84.28 152.37,85.55
PB3-2
  Bottom 0.406: 138.4,32.21 139.67,33.48 151.1,33.48 152.37,34.75
PB4-1
  Bottom 0.406: 135.86,83.01 135.86,84.28 137.13,85.55 149.83,85.55
PB4-2
  Bottom 0.406: 135.86,32.21 135.86,33.48 137.13,34.75 149.83,34.75
PB5-1
  Bottom 0.406: 133.32,83.01 133.32,85.55 134.59,86.82 151.1,86.82 152.37,88.09
PB5-2
  Bottom 0.406: 133.32,32.21 133.32,34.75 134.59,36.02 151.1,36.02 152.37,37.29
PB6-1
  Bottom 0.406: 130.78,83.01 130.78,86.82 132.05,88.09 149.83,88.09
PB6-2
  Bottom 0.406: 130.78,32.21 130.78,36.02 132.05,37.29 149.83,37.29
PB7-1
  Bottom 0.406: 128.24,83.01 128.24,88.09 129.51,89.36 151.1,89.36 152.37,90.63
PB7-2
  Bottom 0.406: 128.24,32.21 128.24,37.29 129.51,38.56 151.1,38.56 152.37,39.83
PC0-1
  Bottom 0.406: 123.16,67.77 123.16,65.23 124.43,63.96 139.67,63.96 146.02,70.31 X2.
PC0-2
  Bottom 0.406: 123.16,16.97 123.16,14.43 124.43,13.16 139.67,13.16 146.02,19.51 X3.
PC1-1
  Bottom 0.406: 125.7,67.77 125.7,66.5 126.97,65.23 139.67,65.23 146.02,71.58 151.1,71.58 152.37,72.85
PC1-2
  Bottom 0.406: 125.7,16.97 125.7,15.7 126.97,14.43 139.67,14.43 146.02,20.78 151.1,20.78 152.37,22.05
PC2-1
  Bottom 0.406: 128.24,67.77 129.51,66.5 139.67,66.5 146.02,72.85 149.83,72.85
PC2-2
  Bottom 0.406: 128.24,16.97 129.51,15.7 139.67,15.7 146.02,22.05 149.83,22.05
PC3-1
  Bottom 0.406: 130.78,67.77 130.78,72.85 132.05,74.12 151.1,74.12 152.37,75.39
PC3-2
  Bottom 0.406: 130.78,16.97 130.78,22.05 132.05,23.32 151.1,23.32 152.37,24.59
PC4-1
  Bottom 0.406: 120.62,67.77 120.62,74.12 121.89,75.39 149.83,75.39
PC4-2
  Bottom 0.406: 120.62,16.97 120.62,23.32 121.89,24.59 149.83,24.59
PC5-1
  Bottom 0.406: 118.08,67.77 118.08,75.39 119.35,76.66 151.1,76.66 152.37,77.93
PC5-2
  Bottom 0.406: 118.08,16.97 118.08,24.59 119.35,25.86 151.1,25.86 152.37,27.13
PC6-1
  Bottom 0.406: 115.54,67.77 115.54,76.66 116.81,77.93 149.83,77.93
PC6-2
  Bottom 0.406: 115.54,16.97 115.54,25.86 116.81,27.13 149.83,27.13
PC7-1
  Bottom 0.406: 113,67.77 113,77.93 114.27,79.2 151.1,79.2 152.37,80.47
PC7-2
  Bottom 0.406: 113,16.97 113,27.13 114.27,28.4 151.1,28.4 152.37,29.67
READ  (via drill 0.61 pad 1.68)
  Top 0.406: 100.3,67.77 v100.3,44.91 100.3,36.02 99.03,34.75 99.03,18.24 100.3,16.97 | 55.85,24.59 53.31,24.59 52.04,25.86 v52.04,44.91
  Bottom 0.406: 19.02,27.13 24.1,27.13 25.37,25.86 49.5,25.86 50.77,24.59 55.85,24.59 | 55.85,75.39 64.74,75.39 66.01,74.12 66.01,72.85 67.28,71.58 81.25,71.58 82.52,70.31 82.52,65.23 83.79,63.96 90.14,63.96 91.41,65.23 91.41,72.85 92.68,74.12 99.03,74.12 100.3,72.85 100.3,67.77 | v52.04,44.91 v100.3,44.91
RESET  (via drill 0.61 pad 1.68)
  Top 0.406: 102.84,83.01 102.84,80.47 104.11,79.2 104.11,36.02 102.84,34.75 102.84,32.21 | 34.26,11.89 32.99,11.89 31.72,13.16 v31.72,30.94
  Bottom 0.406: v31.72,30.94 79.98,30.94 81.25,32.21 81.25,33.48 82.52,34.75 101.57,34.75 102.84,33.48 102.84,32.21
RESET-IN
  Top 0.406: 6.32,28.4 6.32,30.94 7.59,32.21 7.59,36.02 10.13,36.02 | 19.02,16.97 20.29,18.24 20.29,20.78 16.48,20.78 15.21,22.05 15.21,29.67 13.94,30.94 R2.
  Bottom 0.406: 3.78,36.02 10.13,36.02 R2.
VCC  (via drill 0.61 pad 1.68)
  Top 0.406: 125.7,49.99 125.7,52.53 | 126.97,66.5 126.97,69.04 | 126.97,18.24 126.97,15.7 | 11.4,34.75 11.4,37.29 | 12.67,24.59 12.67,27.13 | 54.58,63.96 54.58,61.42 | 85.06,69.04 85.06,66.5 | 85.06,57.61 85.06,55.07 | 85.06,32.21 85.06,29.67
  Top 0.61: 125.7,49.99 125.7,32.21 125.7,27.13 126.97,25.86 126.97,18.24 | 126.97,66.5 125.7,65.23 125.7,52.53 v126.97,52.53 | 126.97,69.04 126.97,79.2 125.7,80.47 125.7,83.01 | v143.48,3 126.97,3 126.97,15.7 | IC4. 6.32,63.96 6.32,57.61 5.05,56.34 M1. | C12. 8.86,57.61 10.13,56.34 V1. 10.13,38.56 11.4,37.29 | 10.13,24.59 12.67,24.59 13.94,23.32 13.94,20.78 15.21,19.51 19.02,19.51 | 11.4,34.75 11.4,32.21 12.67,30.94 12.67,27.13 | IC1. 25.37,69.04 C9. | 54.58,61.42 IC3. | 54.58,63.96 55.85,65.23 57.12,65.23 58.39,66.5 v58.39,77.93 | 83.79,25.86 83.79,28.4 85.06,29.67 | 85.06,66.5 85.06,57.61 | 85.06,55.07 85.06,32.21 | 85.06,69.04 83.79,70.31 C8. | v17.75,61.42 v17.75,65.23
  Bottom 0.406: 83.79,74.12 C8. | 55.85,10.62 55.85,11.89 | 30.45,66.5 32.99,66.5 | 46.96,66.5 49.5,66.5 | C12. 7.59,63.96 IC4. | 72.36,10.62 69.82,10.62 | 68.55,75.39 69.82,74.12 72.36,74.12 | 12.67,61.42 15.21,61.42 | 125.7,29.67 125.7,32.21 | 99.03,30.94 99.03,33.48 88.87,33.48 | 82.52,29.67 82.52,32.21
  Bottom 0.61: 83.79,77.93 83.79,74.12 72.36,74.12 | 55.85,65.23 54.58,66.5 49.5,66.5 | 30.45,66.5 27.91,66.5 C9. | 32.99,66.5 46.96,66.5 | 152.37,60.15 152.37,57.61 149.83,57.61 148.56,57.61 147.29,56.34 147.29,53.8 146.02,52.53 v126.97,52.53 | 152.37,9.35 152.37,6.81 149.83,6.81 149.83,4.27 148.56,3 v143.48,3 | V1. R1. | CPU1. 17.75,5.54 12.67,5.54 11.4,6.81 11.4,18.24 12.67,19.51 19.02,19.51 | 48.23,5.54 48.23,8.08 49.5,9.35 IC2. 55.85,10.62 69.82,10.62 | 72.36,10.62 78.71,10.62 78.71,20.78 C7. 83.79,25.86 82.52,27.13 82.52,29.67 | v58.39,77.93 66.01,77.93 68.55,75.39 | C12. 8.86,61.42 12.67,61.42 | 15.21,61.42 v17.75,61.42 | v17.75,65.23 19.02,65.23 24.1,70.31 IC1. | 125.7,29.67 100.3,29.67 99.03,30.94 | 88.87,33.48 83.79,33.48 82.52,32.21
  pour Top (isolate 0.356): -0.03,99.52 159.99,99.52 159.99,0.46 -0.03,0.46
WRITE  (via drill 0.61 pad 1.68)
  Top 0.406: 100.3,83.01 100.3,80.47 101.57,79.2 v101.57,52.53 101.57,36.02 100.3,34.75 100.3,32.21 | 55.85,62.69 57.12,61.42 v57.12,53.8
  Bottom 0.406: 55.85,62.69 22.83,62.69 21.56,61.42 21.56,55.07 20.29,53.8 17.75,53.8 16.48,52.53 16.48,30.94 17.75,29.67 19.02,29.67 | v101.57,52.53 58.39,52.53 v57.12,53.8

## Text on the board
Top: GND | GND | GND | PB7 | PB6 | PB5 | PB4 | PB3 | 2 | PB1 | 0 | PC7 | 6 | PC5 | PC4 | PC3 | PC2 | PC1 | PC0 | PA7 | PA6 | PA5 | PA4 | PA3 | PA2 | PA1 | VCC | PA0 | VCC | VCC | VCC | A. S. | GND | & | M. P. | GND | GND | GND | PB7 | PB6 | PB5 | PB4 | PB3 | 2 | PB1 | 0 | PC7 | 6 | PC5 | PC4 | PC3 | PC2 | PC1 | PC0 | PA7 | PA6 | PA5 | PA4 | PA3 | PA2 | PA1 | PA0 | VCC | VCC | VCC | Reset
Bottom: A. S. | M. P.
